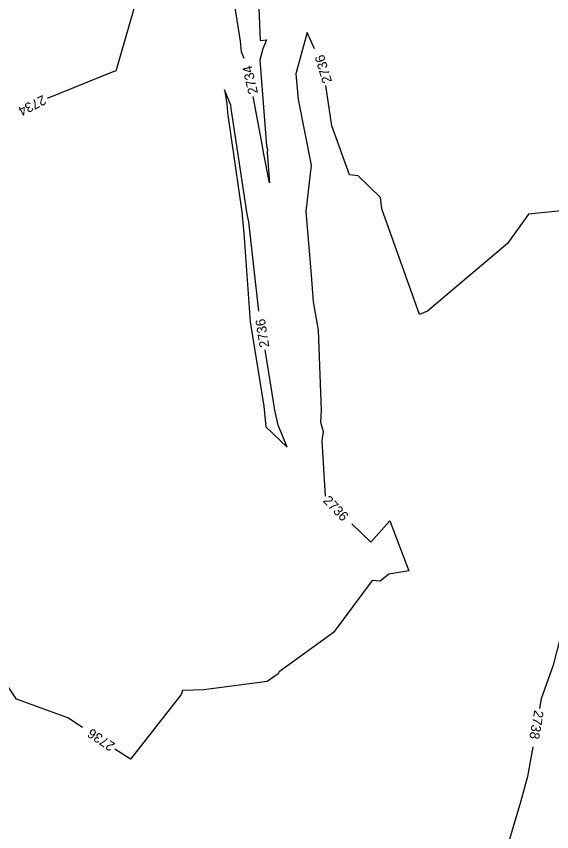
# Model space of a CAD drawing. Extents: x 1326424 to 1329294, y 1001359 to 1003823.
# Drawn here: x 1327991.3 to 1328101.5, y 1002132.9 to 1002300.7 of the extents above; entities that cross this region are included whole.
import ezdxf

# ---------------------------------------------------------------- set-up
doc = ezdxf.new("R2010")
doc.units = 0
doc.layers.add('Scratch_Level_3', color=7, linetype='Continuous')

msp = doc.modelspace()

# ---------------------------------------------------------------- linework, layer by layer
at = {"layer": 'Scratch_Level_3'}
for points in [[(1328038.25, 1002292), (1328037.67, 1002293.4), (1328037.47, 1002295.57), (1328033.95, 1002317.68), (1328031.88, 1002325.13), (1328031.6, 1002330.77), (1328029.13, 1002345.9), (1328027.08, 1002352.28), (1328025.42, 1002357.58), (1328024.26, 1002361.84), (1328023.28, 1002370.25), (1328021.29, 1002373.16), (1328022.53, 1002379.7), (1328021.04, 1002383.34), (1328017.34, 1002380.21), (1328017.65, 1002379.16)], [(1328018.28, 1002371.69), (1328017.82, 1002370.89), (1328015.31, 1002366.8), (1328017.31, 1002360.17), (1328017.46, 1002357.82), (1328018.34, 1002355.03), (1328017.92, 1002351.54), (1328017.34, 1002349.27), (1328016.26, 1002337.61), (1328014.14, 1002327.52), (1328013.8, 1002320.18), (1328016.51, 1002305.91), (1328011.79, 1002289.45), (1328011.39, 1002289.33), (1327997.67, 1002283.83)], [(1328045.84, 1002338.95), (1328044.82, 1002339.62), (1328042.08, 1002341.26), (1328041.62, 1002341.46), (1328041.67, 1002338.23), (1328040.3, 1002325.63), (1328040.55, 1002319.08), (1328041.53, 1002295.71), (1328042.83, 1002295.86), (1328042.04, 1002293.99), (1328041.42, 1002291.71), (1328042.85, 1002274.08), (1328043.01, 1002273.28), (1328042.95, 1002272.71), (1328043.47, 1002266.42), (1328042.23, 1002272.67), (1328042.03, 1002273.98), (1328040.07, 1002284.24)], [(1328052.72, 1002294.04), (1328051.18, 1002297.37), (1328048.89, 1002288.87), (1328049.32, 1002283.58), (1328052, 1002270.12), (1328050.91, 1002260.55), (1328052, 1002247.54), (1328052.42, 1002241.95), (1328053.48, 1002236.17), (1328054.06, 1002219.63), (1328053.94, 1002217.24), (1328054.51, 1002215.28), (1328054.24, 1002213.35), (1328054.92, 1002201.98)], [(1328113.09, 1002261.72), (1328113, 1002261.62), (1328096.75, 1002259.97), (1328092.42, 1002254), (1328076, 1002240.07), (1328074.31, 1002239.33), (1328066.54, 1002261.1), (1328066.32, 1002263.41), (1328061.7, 1002267.92), (1328059.91, 1002268.1), (1328056.3, 1002278.19), (1328055.03, 1002286.46)], [(1328035.45, 1002282.45), (1328034.15, 1002285.6), (1328034.67, 1002282.77), (1328034.81, 1002280.82), (1328037.81, 1002259.97), (1328037.83, 1002259.76), (1328038.16, 1002256.1), (1328039.45, 1002237.86), (1328042.3, 1002220.5), (1328042.7, 1002216.25), (1328047.08, 1002212.09), (1328045.23, 1002216.59), (1328044.56, 1002219.68), (1328042.52, 1002232.12)], [(1328041.26, 1002240.02), (1328039.18, 1002258.42), (1328038.87, 1002259.99), (1328035.58, 1002281.77), (1328035.45, 1002282.45)], [(1328141.65, 1002248), (1328141.14, 1002245.07), (1328139.99, 1002240.41), (1328139.71, 1002239.98), (1328131.71, 1002225.32), (1328125.76, 1002214.25), (1328119.36, 1002203.97), (1328111.12, 1002190.45), (1328109.57, 1002187.58), (1328103.9, 1002175.21), (1328101.84, 1002167.22), (1328099.37, 1002160.26), (1328099.03, 1002158.3)], [(1328060.39, 1002196.3), (1328064.33, 1002192.5), (1328068.22, 1002196.92), (1328072.14, 1002186.65), (1328068.03, 1002185.93), (1328066.25, 1002184.51), (1328064.55, 1002184.62), (1328056.6, 1002173.95), (1328045.41, 1002165.82), (1328045.2, 1002165.46), (1328042.99, 1002163.83), (1328029.91, 1002162.14), (1328025.56, 1002162.01), (1328025.26, 1002161.18), (1328014.82, 1002147.84), (1328011.62, 1002149.95)], [(1328004.95, 1002154.36), (1328001.95, 1002156.35), (1327991.34, 1002160.18), (1327988.18, 1002164.92), (1327965.43, 1002170.91), (1327965.06, 1002171.19), (1327944.8, 1002179.43), (1327938.96, 1002177.53), (1327933.33, 1002177.88), (1327926.28, 1002179.08), (1327915.84, 1002181.56), (1327911.94, 1002181.33)], [(1328097.64, 1002150.42), (1328096.55, 1002144.27), (1328095.09, 1002139.04), (1328090.18, 1002122.39), (1328091.59, 1002115.79), (1328089.59, 1002096.03), (1328088.85, 1002092.22), (1328088.98, 1002091.29), (1328089.13, 1002089.97), (1328088.68, 1002084.16), (1328084.06, 1002078.04), (1328081.21, 1002073.63), (1328080.41, 1002072.06), (1328079.75, 1002068.56), (1328081.21, 1002065.21), (1328078.11, 1002055.2)]]:
    msp.add_lwpolyline(points, dxfattribs=at)

# ---------------------------------------------------------------- texts
for s, rotation, p in [('2736', 106.9447, (1328056.35, 1002287.3)), ('2734', 103.1757, (1328041.1, 1002284.94)), ('2734', 207.1796, (1327996.79, 1002284.58)), ('2736', 99.0667, (1328043.42, 1002232.72)), ('2736', 313.8688, (1328054.33, 1002200.94)), ('2738', 259.9977, (1328097.96, 1002158.03)), ('2736', 146.5279, (1328011.8, 1002151.03))]:
    msp.add_text(s, height=2, rotation=rotation, dxfattribs=at).set_placement(p)

doc.saveas('drawing.dxf')
